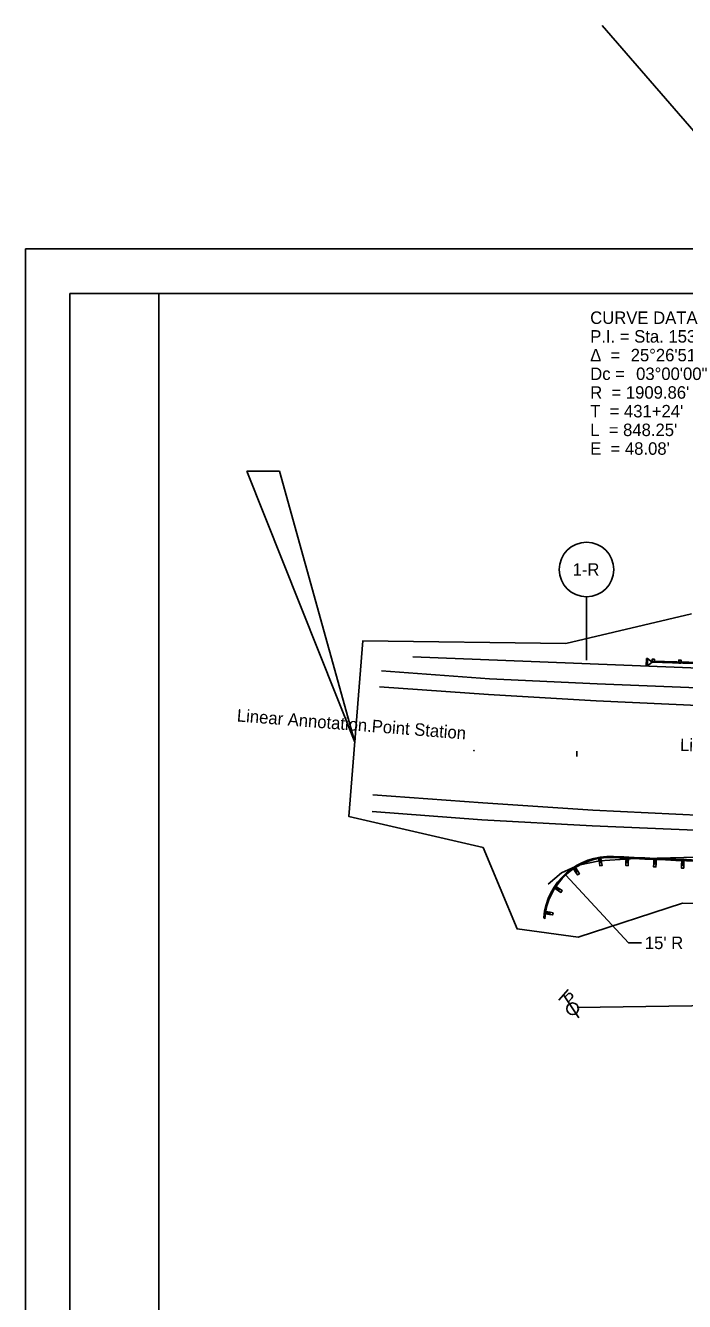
# Model space of a CAD drawing. Extents: x 0 to 1424, y 0 to 866.
# Drawn here: x 744.5 to 892.6, y 543.7 to 830.4 of the extents above; entities that cross this region are included whole.
import ezdxf

# ---------------------------------------------------------------- set-up
doc = ezdxf.new("R2010")
doc.units = 0
for name, color, linetype in [('BR_X_Sub_Backwall', 7, 'Continuous'), ('DT_P_Slope_Break_Line', 7, 'Continuous'), ('GE_P_Alignment_100_Bearings', 7, 'Continuous'), ('GE_P_Alignment_100_Distances', 7, 'Continuous'), ('GE_X_Alignment_100_Stations', 7, 'Continuous'), ('GE_X_Alignment_500_Stations', 7, 'Continuous'), ('HY_X_Water_Edge', 7, 'Continuous'), ('MT_P_Edge_Line', 7, 'Continuous'), ('MT_P_Stop_Line', 7, 'Continuous'), ('PF_P_Grade_Line', 7, 'Continuous'), ('RD_P_GR_Lt', 7, 'Continuous'), ('RD_P_GR_Rt', 7, 'Continuous'), ('SH_Named_Boundary', 7, 'Continuous'), ('TX_P_1', 7, 'Continuous'), ('TX_X_1', 7, 'Continuous')]:
    doc.layers.add(name, color=color, linetype=linetype)

msp = doc.modelspace()

# ---------------------------------------------------------------- linework, layer by layer
at = {"layer": 'BR_X_Sub_Backwall'}
for points in [[(824.02, 681.8), (848.55, 680.09), (872.69, 678.71), (897.23, 677.55), (922.51, 676.8), (947.05, 676.41), (971.06, 676.33), (996.17, 676.44), (1020.51, 676.86), (1045.53, 677.69), (1069.94, 678.84), (1094.68, 680.31), (1118.73, 682.11), (1143.22, 684.24), (1168.04, 686.67), (1192.24, 689.47), (1216.36, 692.42)], [(1220.52, 668.15), (1195.56, 664.98), (1171.02, 662.21), (1146.24, 659.63), (1121.92, 657.46), (1096.96, 655.52), (1072.21, 653.97), (1047.24, 652.83), (1021.71, 652.1), (996.95, 651.5), (972.25, 651.31), (947.23, 651.51), (922.22, 651.93), (896.85, 652.91), (871.97, 654.14), (847.27, 655.73), (822.55, 657.56)]]:
    msp.add_lwpolyline(points, dxfattribs=at)
at = {"layer": 'DT_P_Slope_Break_Line'}
msp.add_lwpolyline([(868.47, 609.78), (920.02, 610.51), (952.42, 610.79), (979.59, 610.93), (999.02, 611.08), (1014.52, 611.18), (1054.77, 611.28), (1101.52, 611.45)], dxfattribs=at)
at = {"layer": 'GE_P_Alignment_100_Bearings'}
for p, q in [((874.07, 830.43), (1330.4, 303.64)), ((801.57, 730.26), (794.22, 730.26)), ((870.55, 687.81), (870.55, 702.05)), ((865.87, 639.53), (879.99, 624.29)), ((879.99, 624.29), (882.91, 624.29))]:
    msp.add_line(p, q, dxfattribs=at)
msp.add_lwpolyline([(794.22, 730.26), (818.45, 669.41), (801.57, 730.26)], dxfattribs=at)
msp.add_circle((870.55, 708.18), 6.13, dxfattribs=at)
at = {"layer": 'GE_X_Alignment_100_Stations'}
for p, q in [((818.45, 669.41), (818.61, 671.4)), ((868.34, 666.14), (868.41, 667.34))]:
    msp.add_line(p, q, dxfattribs=at)
for points in [[(754.45, 770.24), (774.45, 770.24), (774.45, 350.24), (754.45, 350.24)], [(774.45, 770.24), (1414.45, 770.24), (1414.45, 350.24), (774.45, 350.24)]]:
    msp.add_lwpolyline(points, close=True, dxfattribs=at)
at = {"layer": 'GE_X_Alignment_500_Stations'}
msp.add_line((818.45, 669.41), (818.55, 670.6), dxfattribs=at)
at = {"layer": 'HY_X_Water_Edge'}
msp.add_lwpolyline([(922.28, 685), (867.59, 687.13), (831.54, 688.53)], dxfattribs=at)
at = {"layer": 'MT_P_Edge_Line'}
msp.add_lwpolyline([(921.68, 643.69), (909.32, 643.99), (892.41, 643.44), (880.47, 643.18), (873.45, 642.75), (868.74, 641.76), (864.93, 640.06), (861.95, 637.45)], dxfattribs=at)
at = {"layer": 'MT_P_Stop_Line'}
for p, q in [((866.42, 613.79), (864.3, 611.39)), ((865.36, 612.59), (868.8, 607.42)), ((865.7, 612.07), (866.27, 612.71)), ((866.44, 610.97), (867.22, 611.87))]:
    msp.add_line(p, q, dxfattribs=at)
msp.add_circle((867.43, 609.49), 1.3, dxfattribs=at)
msp.add_arc((866.75, 612.3), 0.638, 317.516, 139.7626, dxfattribs=at)
at = {"layer": 'PF_P_Grade_Line'}
msp.add_circle((845.27, 667.49), 0.034, dxfattribs=at)
at = {"layer": 'RD_P_GR_Lt'}
for p, q in [((883.98, 686.55), (884.03, 688.22)), ((884.28, 688.21), (884.03, 688.22)), ((884.18, 686.55), (884.23, 688.21)), ((884.23, 686.54), (884.28, 688.21)), ((884.28, 688.21), (885.28, 687.35)), ((884.23, 686.54), (883.98, 686.55)), ((884.23, 686.54), (885.28, 687.35)), ((938.39, 685.76), (885.28, 687.35)), ((938.39, 686.01), (885.29, 687.6))]:
    msp.add_line(p, q, dxfattribs=at)
for points in [[(885.78, 687.33), (885.28, 687.35), (885.3, 688.01), (885.8, 688)], [(891.78, 687.15), (891.28, 687.17), (891.3, 687.83), (891.8, 687.82)]]:
    msp.add_lwpolyline(points, close=True, dxfattribs=at)
at = {"layer": 'RD_P_GR_Rt'}
for p, q in [((873.78, 643.31), (873.28, 643.23)), ((873.44, 642.25), (873.28, 643.23)), ((873.94, 642.33), (873.28, 643.23)), ((873.44, 642.25), (873.78, 643.31)), ((873.94, 642.33), (873.78, 643.31)), ((879.42, 642.31), (879.47, 643.31)), ((879.42, 642.31), (879.97, 643.28)), ((879.97, 643.28), (879.47, 643.31)), ((879.92, 642.28), (879.47, 643.31)), ((879.92, 642.28), (879.97, 643.28)), ((885.67, 642.03), (885.71, 643.03)), ((885.67, 642.03), (886.21, 643.01)), ((886.21, 643.01), (885.71, 643.03)), ((886.17, 642.01), (885.71, 643.03)), ((886.17, 642.01), (886.21, 643.01)), ((891.92, 641.77), (891.96, 642.77)), ((891.92, 641.77), (892.46, 642.75)), ((892.46, 642.75), (891.96, 642.77)), ((892.42, 641.75), (891.96, 642.77)), ((892.42, 641.75), (892.46, 642.75)), ((868.05, 641.21), (867.63, 640.94)), ((868.18, 640.1), (867.63, 640.94)), ((868.6, 640.37), (867.63, 640.94)), ((868.6, 640.37), (868.05, 641.21)), ((868.18, 640.1), (868.05, 641.21)), ((863.67, 636.97), (863.39, 636.55)), ((864.23, 636), (863.39, 636.55)), ((864.5, 636.42), (863.39, 636.55)), ((864.5, 636.42), (863.67, 636.97)), ((864.23, 636), (863.67, 636.97)), ((861.37, 631.31), (861.29, 630.82)), ((862.36, 631.15), (861.29, 630.82)), ((862.28, 630.66), (861.29, 630.82)), ((862.36, 631.15), (861.37, 631.31)), ((862.28, 630.66), (861.37, 631.31)), ((860.95, 629.96), (861.17, 629.67))]:
    msp.add_line(p, q, dxfattribs=at)
for points in [[(873.44, 642.25), (873.94, 642.33), (874.05, 641.67), (873.55, 641.59)], [(879.42, 642.31), (879.92, 642.28), (879.89, 641.62), (879.39, 641.64)], [(868.18, 640.1), (868.6, 640.37), (868.96, 639.81), (868.54, 639.54)], [(885.67, 642.03), (886.17, 642.01), (886.14, 641.34), (885.64, 641.36)], [(891.92, 641.77), (892.42, 641.75), (892.39, 641.09), (891.89, 641.11)], [(864.23, 636), (864.5, 636.42), (865.06, 636.06), (864.79, 635.64)], [(862.28, 630.66), (862.36, 631.15), (863.02, 631.04), (862.94, 630.55)]]:
    msp.add_lwpolyline(points, close=True, dxfattribs=at)
for centre, radius, start, end in [((875.89, 628.71), 15, 87.2796, 175.2476), ((875.89, 628.71), 14.75, 87.2796, 176.3007), ((968.3, 2573.38), 1932.11, 267.27958, 268.39176), ((968.3, 2573.38), 1931.86, 267.27957, 268.39176)]:
    msp.add_arc(centre, radius, start, end, dxfattribs=at)
at = {"layer": 'SH_Named_Boundary'}
msp.add_lwpolyline([(744.45, 340.24), (1424.45, 340.24), (1424.45, 780.24), (744.45, 780.24)], close=True, dxfattribs=at)
at = {"layer": 'TX_P_1'}
for points in [[(824.45, 685.38), (848.71, 683.65), (872.94, 682.49), (897.31, 681.54), (922.75, 680.59), (947.11, 680.25), (971.2, 680.27), (996.18, 680.35), (1020.4, 680.63), (1045.46, 681.64), (1069.73, 682.81), (1080.26, 683.8), (1094.6, 683.9), (1108.74, 685.27), (1112.46, 686.53), (1118.53, 686.7), (1125.87, 687.13), (1129.02, 686.38), (1143.02, 687.32), (1167.77, 689.75), (1191.96, 692.49), (1216.02, 695.75)], [(896.72, 649.56), (871.84, 650.59), (847.01, 651.94), (822.34, 653.8)]]:
    msp.add_lwpolyline(points, dxfattribs=at)
at = {"layer": 'TX_X_1'}
for points in [[(894.15, 698.22), (865.93, 691.59), (820.24, 692.12), (817.13, 652.67), (847.35, 645.73)], [(892.1, 633.22), (868.64, 625.59), (854.96, 627.42), (847.35, 645.73)], [(892.1, 633.22), (916.58, 632.54), (941.07, 615.69), (968.88, 598.84)]]:
    msp.add_lwpolyline(points, dxfattribs=at)

# ---------------------------------------------------------------- texts
at = {"layer": 'GE_P_Alignment_100_Bearings'}
for s, p in [('1-R', (867.42, 706.78)), ("15' R", (883.66, 622.89))]:
    msp.add_text(s, height=2.8, dxfattribs=at).set_placement(p)
at = {"layer": 'GE_P_Alignment_100_Distances'}
for s, p in [('CURVE DATA', (871.38, 763.37)), ('P.I. = Sta. 1531+13.59', (871.38, 759.17)), ('Δ  = ', (871.38, 754.97)), ('25°26\'51" LT', (880.48, 754.97)), ('Dc = ', (871.38, 750.77)), ('03°00\'00"', (881.7, 750.77)), ("R  = 1909.86'", (871.38, 746.57)), ("T  = 431+24'", (871.38, 742.37)), ("L  = 848.25'", (871.38, 738.17)), ("E  = 48.08'", (871.38, 733.97))]:
    msp.add_text(s, height=2.8, dxfattribs=at).set_placement(p)
at = {"layer": 'GE_X_Alignment_100_Stations'}
for rotation, p in [(355.5, (791.89, 674.05)), (358.5, (891.54, 667.42))]:
    msp.add_text('Linear Annotation.Point Station', height=2.8, rotation=rotation, dxfattribs=at).set_placement(p)

doc.saveas('drawing.dxf')
